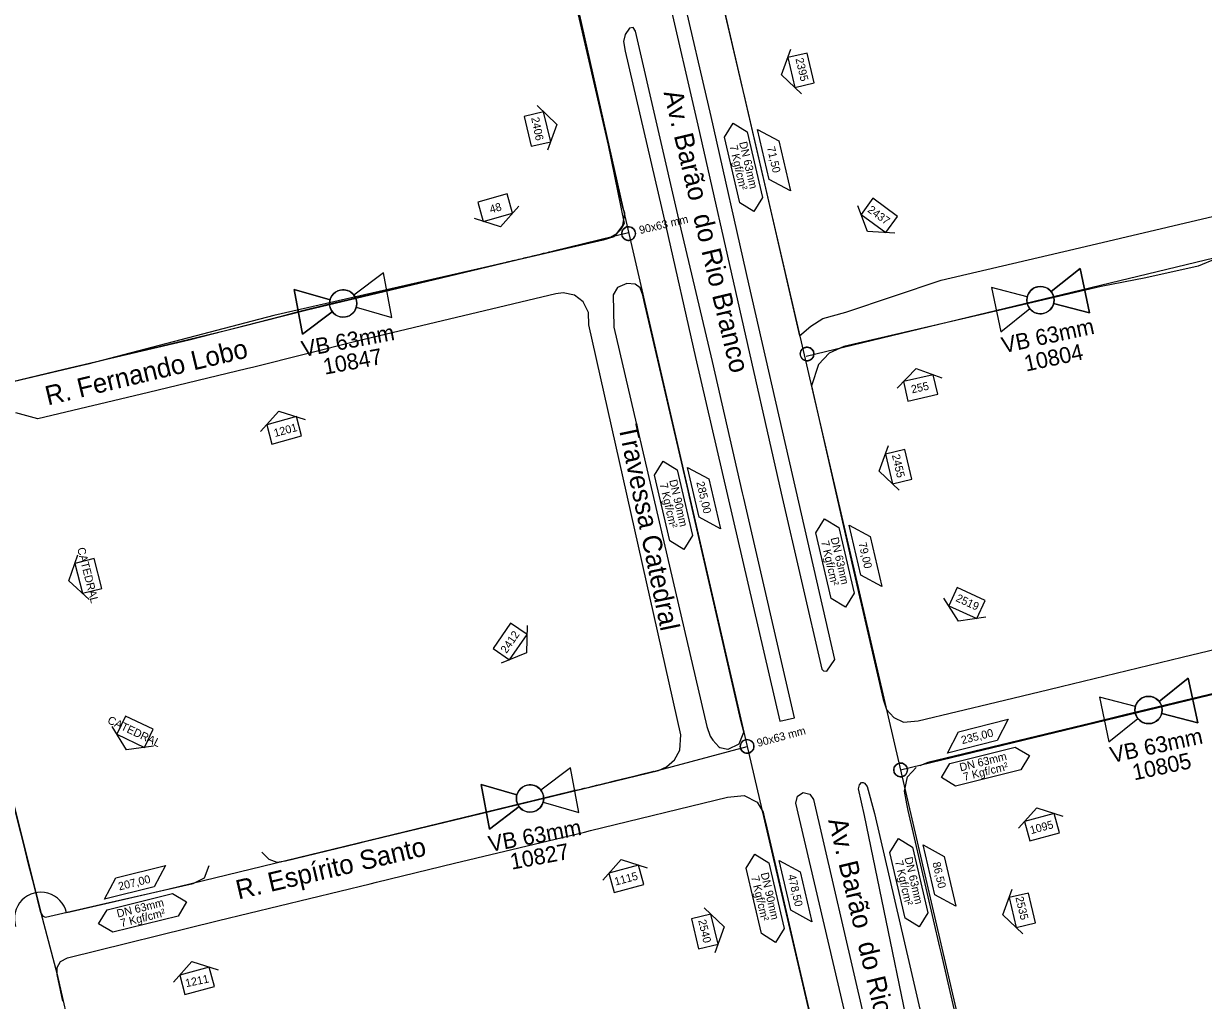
# Model space of a CAD drawing. Extents: x 656692 to 673945, y 7585994 to 7599066.
# Drawn here: x 670030 to 670472.2, y 7593362 to 7593728.2 of the extents above; entities that cross this region are included whole.
import ezdxf

# ---------------------------------------------------------------- set-up
doc = ezdxf.new("R2010")
doc.units = 0
for name, color, linetype in [('FORMATO', 7, 'Continuous'), ('LOGRADOURO', 7, 'Continuous'), ('LOGRADOURO_TEXTO', 7, 'Continuous'), ('NUM_REF', 7, 'Continuous'), ('SIMBOLO', 7, 'Continuous'), ('TEXTO', 7, 'Continuous'), ('TUBO_PEAD_GN_63', 7, 'Continuous'), ('TUBO_PEAD_GN_90', 7, 'Continuous'), ('VALVULA_PEAD_63', 7, 'Continuous')]:
    doc.layers.add(name, color=color, linetype=linetype)

# ---------------------------------------------------------------- blocks, each defined once
blk = doc.blocks.new('INTERLIGACAO_5')
at = {"layer": 'SIMBOLO'}
blk.add_circle((0, 0), 1.28, dxfattribs=at)
for start, end in [(0, 180), (180, 0)]:
    blk.add_arc((0, 0), 1.28, start, end, dxfattribs=at)
blk = doc.blocks.new('VALVULA_PEAD_DN_9')
at = {"layer": 'VALVULA_PEAD_63'}
for points in [[(-1.14, 0.57), (-4.25, 2.13), (-4.25, -2.13), (-1.14, -0.57)], [(-1.14, -0.57), (-4.25, -2.13), (-4.25, 2.13), (-1.14, 0.57)], [(1.14, -0.57), (4.25, -2.13), (4.25, 2.13), (1.14, 0.57)], [(1.14, -0.57), (4.25, -2.13), (4.25, 2.13), (1.14, 0.57)]]:
    blk.add_lwpolyline(points, dxfattribs=at)
blk.add_circle((0, 0), 1.28, dxfattribs=at)
for start, end in [(90, 270), (270, 90), (153.4349, 206.5651), (0, 26.5651), (333.4349, 0)]:
    blk.add_arc((0, 0), 1.28, start, end, dxfattribs=at)
blk = doc.blocks.new('NUM_REF_1')
at = {"layer": 'NUM_REF'}
blk.add_lwpolyline([(-4.3125, 0.9375), (0, 3.75), (4.3125, 0.9375)], dxfattribs=at)
blk.add_lwpolyline([(2.875, -1.875), (2.875, 1.875), (-2.875, 1.875), (-2.875, -1.875)], close=True, dxfattribs=at)

msp = doc.modelspace()

# ---------------------------------------------------------------- linework, layer by layer
at = {"layer": 'LOGRADOURO'}
for p, q in [((670024.02, 7593444.94), (670031.73, 7593414.01)), ((670031.73, 7593414.01), (670032.49, 7593410.8)), ((670032.49, 7593410.8), (670036.58, 7593394.65)), ((670097.78, 7593407.98), (670099.58, 7593412.58)), ((670060.51, 7593398.35), (670093.53, 7593405.81)), ((670093.53, 7593405.81), (670097.78, 7593407.98)), ((670038.28, 7593393.24), (670060.51, 7593398.35)), ((670036.58, 7593394.65), (670037.26, 7593393.55)), ((670037.26, 7593393.55), (670038.28, 7593393.24))]:
    msp.add_line(p, q, dxfattribs=at)
for points in [[(670136.66, 7594169.86), (670162.19, 7594059.36), (670168.87, 7594029.73), (670175.31, 7594002.75), (670179.99, 7593982.77), (670184.4, 7593962.89), (670195.03, 7593917.13), (670204.21, 7593877.89), (670211.92, 7593844.99), (670217.01, 7593822.85), (670221.54, 7593803.12), (670225.32, 7593786.75), (670233.29, 7593752.31), (670242.08, 7593714.06), (670247.91, 7593688.8), (670255.04, 7593653.23), (670253.88, 7593651.05), (670251.21, 7593648.31), (670247.27, 7593647.06), (670216.98, 7593640), (670123.81, 7593618.77), (670054.05, 7593600.53), (670014.86, 7593591.25)], [(670236.15, 7593644.74), (670238.98, 7593645.42), (670241.53, 7593645.89), (670250.03, 7593648.17), (670252.4, 7593649.57), (670254.58, 7593652.54), (670255.31, 7593657.11), (670254.61, 7593659.28), (670234.33, 7593747.36), (670233.58, 7593750.06), (670216.99, 7593822.33), (670208.09, 7593860.47), (670207.48, 7593863.14), (670194.62, 7593918.2)], [(670290.86, 7593740.61), (670299.36, 7593704.14), (670299.9, 7593701.63), (670307.04, 7593670.92), (670320.78, 7593611.18), (670325.01, 7593614.78), (670329.56, 7593617.6), (670338.18, 7593620.03), (670373.95, 7593632), (670423.55, 7593643.65), (670476.13, 7593656.05), (670516.11, 7593665.38), (670567.2, 7593677.24), (670616.08, 7593688.7), (670660.58, 7593699.2), (670708.06, 7593710.35), (670743.57, 7593718.73)], [(670052.85, 7593600.41), (670106.22, 7593613.27), (670111.71, 7593614.61), (670136.24, 7593620.95), (670175.63, 7593630.32), (670218.05, 7593640.34), (670229.18, 7593643.04)], [(670476.87, 7593640), (670470.14, 7593637.23), (670450.59, 7593632.96), (670433.82, 7593629.66), (670388.45, 7593619.06), (670337.43, 7593607.12), (670331.9, 7593604.61), (670327.91, 7593600.47), (670325.25, 7593592.36), (670343.34, 7593513.28), (670343.94, 7593510.7), (670352.1, 7593474.83), (670353.38, 7593471.02), (670356.19, 7593468.05), (670359.76, 7593466.37), (670365.33, 7593466.79), (670394.54, 7593473.78)], [(670119.3, 7593417.6), (670121.96, 7593414.92), (670124.99, 7593413.82), (670128.24, 7593414.3), (670155.54, 7593421), (670157.91, 7593421.59), (670201.54, 7593432.13), (670237.04, 7593440.77), (670239.57, 7593441.3), (670268.02, 7593448.27), (670271.01, 7593449.56), (670274, 7593452.26), (670275.9, 7593455.83), (670276.3, 7593461.63), (670241.81, 7593615.3), (670241.68, 7593619.9), (670239.77, 7593623.87), (670236.44, 7593626.41), (670232.26, 7593627.27), (670229.49, 7593626.87), (670197.55, 7593619.24), (670155, 7593609.11), (670116.28, 7593599.46), (670113.61, 7593598.79), (670076.8, 7593589.97), (670035.32, 7593580.07), (670027.12, 7593582.27)], [(670624.53, 7593346.32), (670665.62, 7593355.7), (670667.59, 7593356.09), (670697.27, 7593362.61), (670702.8, 7593365.37), (670705.69, 7593368.66), (670706.88, 7593370.4), (670708.67, 7593375.24), (670708.85, 7593377.49), (670708.47, 7593380.98), (670699.83, 7593416.77), (670686.44, 7593472.31), (670676.15, 7593514.65), (670664.58, 7593522.51), (670662.69, 7593522.28), (670659.9, 7593521.61), (670621.54, 7593512.36), (670576.82, 7593501.52), (670519.17, 7593487.47), (670442.25, 7593468.96), (670430.14, 7593466), (670368.87, 7593451.23), (670365.85, 7593449.92)], [(670394.54, 7593473.78), (670414.28, 7593478.6), (670418.83, 7593479.69), (670464.25, 7593490.68), (670523.46, 7593504.9), (670525.68, 7593505.41)], [(670624.53, 7593346.32), (670569.73, 7593334.07), (670521.66, 7593323.42), (670475.94, 7593313.21), (670447.99, 7593307.01), (670409.67, 7593298.01), (670407.35, 7593294.02), (670395.17, 7593291.1), (670382.94, 7593340.67), (670382.41, 7593343.17), (670373.98, 7593379.53), (670373.43, 7593381.99), (670361.58, 7593433.22), (670360.99, 7593435.72), (670360.19, 7593440.5), (670361.29, 7593445.84), (670364.54, 7593449.36)], [(670368.76, 7593316.87), (670345.18, 7593431.32), (670342.86, 7593441.38), (670343.24, 7593442.85), (670344.05, 7593443.72), (670344.62, 7593443.73), (670345.2, 7593443.52), (670346.15, 7593442.22), (670348.9, 7593432.15), (670362.09, 7593374.99), (670378.38, 7593304.57)], [(670103.06, 7593391.93), (670159.88, 7593405.67), (670162.27, 7593406.41), (670191.57, 7593413.43), (670240.19, 7593425.15), (670242.51, 7593425.69), (670293.82, 7593438.22), (670300.05, 7593438.85), (670304.88, 7593436.29), (670307.19, 7593432.6), (670307.57, 7593430.88), (670308.2, 7593428.29), (670319.92, 7593377.44), (670330.4, 7593332.55)], [(670370.49, 7593216.23), (670365.31, 7593239.19), (670356.94, 7593275.23), (670346.89, 7593317.85), (670337.18, 7593360.24), (670319.46, 7593435.91), (670320.05, 7593438.64), (670322.19, 7593439.95), (670324.67, 7593439.35), (670325.99, 7593437.38), (670344.66, 7593356.88), (670345.13, 7593355.18), (670357.38, 7593302.46), (670359.16, 7593289.89), (670371.72, 7593216.66), (670383.02, 7593167.92), (670394.57, 7593117.88), (670408.28, 7593058.99), (670415.84, 7593026.27)], [(670044.71, 7593361.7), (670042.62, 7593371.71), (670042.65, 7593374.39), (670043.81, 7593376.6), (670046.45, 7593378.02), (670103.06, 7593391.93)]]:
    msp.add_lwpolyline(points, dxfattribs=at)
for points in [[(670334.05, 7593489.79), (670318.17, 7593559.19), (670301.86, 7593630.62), (670287.68, 7593693.43), (670276.55, 7593741.29), (670275.57, 7593742), (670274.72, 7593741.95), (670272.16, 7593741.39), (670271.35, 7593740.54), (670271.34, 7593739.5), (670282.74, 7593690.13), (670313.95, 7593552.18), (670329.17, 7593486.16), (670329.83, 7593485.58), (670331.04, 7593485.47)], [(670259.33, 7593725.35), (670258.42, 7593726.69), (670257.11, 7593726.44), (670255.52, 7593724.08), (670254.89, 7593721.51), (670255.52, 7593717.82), (670270.76, 7593652.27), (670281.89, 7593603.01), (670313.49, 7593466.65), (670318.89, 7593467.9), (670299.94, 7593550.36), (670299.47, 7593552.3), (670288.25, 7593601.49), (670275.98, 7593653.23)], [(670286.08, 7593464.66), (670287.34, 7593461.1), (670288.34, 7593459.61), (670290.54, 7593457.07), (670290.93, 7593456.85), (670294, 7593456.15), (670294.07, 7593456.2), (670298.16, 7593458.16), (670299.9, 7593462.61), (670299.44, 7593464.52), (670298.78, 7593466.97), (670279.64, 7593550.8), (670279.08, 7593553.13), (670262.6, 7593624.07), (670262.04, 7593626.41), (670261.14, 7593629.11), (670259.17, 7593630.47), (670256.04, 7593630.8), (670252.58, 7593629.3), (670251, 7593626.49), (670251.2, 7593614.44)]]:
    msp.add_lwpolyline(points, close=True, dxfattribs=at)
at = {"layer": 'SIMBOLO'}
for points in [[(670295.93, 7593690.88), (670301.19, 7593687.61), (670306.95, 7593663.03), (670303.69, 7593657.77), (670298.43, 7593661.03), (670292.67, 7593685.62), (670295.93, 7593690.88)], [(670269.74, 7593564.2), (670274.99, 7593560.94), (670280.73, 7593536.35), (670277.47, 7593531.1), (670272.21, 7593534.36), (670266.47, 7593558.95), (670269.74, 7593564.2)], [(670330.22, 7593542.56), (670335.48, 7593539.3), (670341.24, 7593514.71), (670337.98, 7593509.46), (670332.72, 7593512.72), (670326.96, 7593537.3), (670330.22, 7593542.56)], [(670373.97, 7593445.56), (670377.16, 7593450.87), (670401.66, 7593456.97), (670406.96, 7593453.78), (670403.77, 7593448.48), (670379.27, 7593442.38), (670373.97, 7593445.56)], [(670357.93, 7593422.69), (670363.19, 7593419.43), (670368.95, 7593394.84), (670365.69, 7593389.58), (670360.43, 7593392.85), (670354.67, 7593417.43), (670357.93, 7593422.69)], [(670304.02, 7593416.89), (670309.28, 7593413.62), (670315.02, 7593389.03), (670311.75, 7593383.78), (670306.5, 7593387.05), (670300.76, 7593411.63), (670304.02, 7593416.89)], [(670058.12, 7593390.73), (670061.31, 7593396.04), (670085.81, 7593402.14), (670091.11, 7593398.95), (670087.92, 7593393.65), (670063.42, 7593387.55), (670058.12, 7593390.73)]]:
    msp.add_lwpolyline(points, dxfattribs=at)
for points in [[(670309.47, 7593669.8), (670305.09, 7593688.51), (670313.03, 7593684.21), (670317.41, 7593665.5)], [(670283.26, 7593543.12), (670278.89, 7593561.83), (670286.83, 7593557.53), (670291.2, 7593538.81)], [(670343.76, 7593521.48), (670339.38, 7593540.2), (670347.32, 7593535.89), (670351.7, 7593517.18)], [(670394.86, 7593459.4), (670376.21, 7593454.75), (670380.4, 7593462.75), (670399.05, 7593467.4)], [(670371.47, 7593401.61), (670367.09, 7593420.32), (670375.03, 7593416.02), (670379.41, 7593397.31)], [(670317.55, 7593395.8), (670313.18, 7593414.52), (670321.11, 7593410.21), (670325.48, 7593391.49)], [(670079, 7593404.57), (670060.36, 7593399.92), (670064.55, 7593407.92), (670083.2, 7593412.57)]]:
    msp.add_lwpolyline(points, close=True, dxfattribs=at)
at = {"layer": 'TUBO_PEAD_GN_63'}
for p, q in [((670358.69, 7593448.43), (670738.73, 7593540.54)), ((670266.18, 7593447.81), (670301.15, 7593457.23)), ((670084.08, 7593403.63), (670046.23, 7593394.88))]:
    msp.add_line(p, q, dxfattribs=at)
for points in [[(670270.63, 7593828.18), (670395.17, 7593291.1), (670412.62, 7593214.31), (670425.77, 7593159.21), (670458.65, 7593013.14)], [(670036.5, 7593394.83), (670033.94, 7593405.1), (670031.92, 7593413.12), (670030, 7593420.91), (670028.04, 7593428.76), (670026.15, 7593436.44), (670024, 7593445.14), (670021.9, 7593454.01), (670019.78, 7593463.14), (670018.49, 7593468.48), (670017.25, 7593473.7), (670016.34, 7593477.75), (670014.68, 7593485.08), (670012.07, 7593496.69), (670009.27, 7593509.09), (670007.08, 7593519.11), (670004.85, 7593529.26), (670002.82, 7593538.9), (670000.97, 7593547.38), (669998.98, 7593556.44), (669996.99, 7593565.7), (669995.51, 7593572.61), (669992.66, 7593585.75), (669931.57, 7593813.26)], [(670876.88, 7593732.22), (670593.65, 7593668.61), (670323.25, 7593603.37)], [(670256.7, 7593649.76), (670228.59, 7593642.9), (670227.75, 7593642.7), (670226.9, 7593642.49), (670226.21, 7593642.32), (670225.7, 7593642.2), (670224.79, 7593641.98), (670223.95, 7593641.78), (670223.15, 7593641.58), (670222.47, 7593641.42), (670221.96, 7593641.29), (670221.4, 7593641.16), (670220.73, 7593640.99), (670220.05, 7593640.83), (670219.37, 7593640.66), (670218.78, 7593640.52), (670218.13, 7593640.36), (670217.52, 7593640.21), (670216.92, 7593640.08), (670216.21, 7593639.91), (670215.52, 7593639.74), (670214.71, 7593639.55), (670213.98, 7593639.38), (670213.23, 7593639.21), (670212.5, 7593639.03), (670211.8, 7593638.86), (670211.18, 7593638.72), (670210.57, 7593638.57), (670209.75, 7593638.38), (670204.38, 7593637.12), (670199.05, 7593635.86), (670194.77, 7593634.85), (670189.56, 7593633.61), (670184.76, 7593632.49), (670180.86, 7593631.55), (670177.28, 7593630.73), (670171.16, 7593629.26), (670165.44, 7593627.89), (670160.6, 7593626.75), (670155.75, 7593625.61), (670151.81, 7593624.66), (670147.27, 7593623.59), (670143.16, 7593622.61), (670140.15, 7593621.88), (670137.49, 7593621.24), (670134.61, 7593620.54), (670132.06, 7593619.87), (670129.31, 7593619.17), (670126.53, 7593618.45), (670092.03, 7593609.58), (670045.08, 7593598.51), (670002.33, 7593588.33)], [(670266.18, 7593447.81), (670266.14, 7593447.81), (670265.16, 7593447.56), (670262.14, 7593446.82), (670258.19, 7593445.87), (670254.45, 7593444.94), (670251.3, 7593444.17), (670250.36, 7593443.94), (670249.06, 7593443.63), (670247.83, 7593443.32), (670246.93, 7593443.1), (670245.95, 7593442.87), (670245.37, 7593442.72), (670244.63, 7593442.54), (670243.84, 7593442.34), (670243.26, 7593442.2), (670242.4, 7593441.99), (670241.92, 7593441.87), (670241.42, 7593441.75), (670241.02, 7593441.65), (670240.04, 7593441.41), (670239.49, 7593441.28), (670239.1, 7593441.2), (670238.8, 7593441.13), (670237.61, 7593440.89), (670237.08, 7593440.77), (670236.62, 7593440.66), (670236.11, 7593440.54), (670235.76, 7593440.45), (670235.28, 7593440.34), (670235.21, 7593440.32), (670235.16, 7593440.31), (670235.08, 7593440.29), (670235.02, 7593440.27), (670234.92, 7593440.25), (670234.86, 7593440.23), (670234.79, 7593440.22), (670234.69, 7593440.19), (670084.1, 7593403.63)], [(670036.49, 7593394.84), (670042.62, 7593371.71), (670056.94, 7593308.46), (670060.28, 7593293.62), (670061.17, 7593289.64), (670063.93, 7593277.91), (670115.31, 7593058.49), (670129.76, 7592973.31), (670135.69, 7592949.71), (670140.2, 7592938.17), (670145.14, 7592928.13), (670154.31, 7592914.73), (670168.41, 7592898.93), (670188.86, 7592877.64), (670202.82, 7592863.12)]]:
    msp.add_lwpolyline(points, dxfattribs=at)
msp.add_arc((670036.5, 7593392.62), 9.93, 13.2191, 196.6626, dxfattribs=at)
at = {"layer": 'TUBO_PEAD_GN_90'}
msp.add_lwpolyline([(670197.11, 7593914.53), (670254.61, 7593659.28), (670299.9, 7593462.61), (670366.09, 7593178.46), (670413.3, 7592972.1)], dxfattribs=at)

# ---------------------------------------------------------------- block references
at = {"layer": 'FORMATO'}
for p, xscale, yscale, rotation in [((670321.38, 7593710.7), 2, 2, 103.25233689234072), ((670222.6, 7593688.67), 2, 2, -76.67539240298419), ((670206.76, 7593659.2), 1.9999999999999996, 1.9999999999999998, -164.43974362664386), ((670350.73, 7593656.29), 2, 2, 143.8193996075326), ((670366.17, 7593591.63), 2, 2, 12.737713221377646), ((670127.69, 7593575.73), 2, 2, 15.171414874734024), ((670357.97, 7593562.12), 2, 2, 103.25233689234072), ((670054.28, 7593521.15), 1.9999999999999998, 1.9999999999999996, 104.2104213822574), ((670383.56, 7593510.97), 1.9999999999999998, 2.0000000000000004, 155.3437654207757), ((670212.35, 7593496.58), 1.9999999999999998, 1.9999999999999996, -124.58320234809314), ((670071.79, 7593462.75), 2, 2, 154.51740502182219), ((670411.7, 7593426.99), 2, 2, 15.171414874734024), ((670255.94, 7593407.6), 2, 2, 15.171414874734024), ((670404.29, 7593395.82), 2, 2, 103.25233689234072), ((670285.29, 7593387.88), 2, 2, -76.67539240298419), ((670095.06, 7593369.36), 2, 2, 15.171414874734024)]:
    msp.add_blockref('NUM_REF_1', p, dxfattribs=dict(at, xscale=xscale, yscale=yscale, rotation=rotation))
at = {"layer": 'SIMBOLO'}
for p, xscale, yscale, rotation in [((670256.74, 7593649.5), 1.9999999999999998, 2.0000000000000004, -152.2575551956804), ((670323.63, 7593604.35), 2, 2, -14.764722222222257), ((670301.15, 7593457.23), 2, 2, 67.86674283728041), ((670358.69, 7593448.43), 2, 2, -14.764722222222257)]:
    msp.add_blockref('INTERLIGACAO_5', p, dxfattribs=dict(at, xscale=xscale, yscale=yscale, rotation=rotation))
at = {"layer": 'VALVULA_PEAD_63', "yscale": 4.000000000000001}
for p, xscale, rotation in [((670411.1, 7593624.54), 4.000000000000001, -167.8897304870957), ((670149.76, 7593623.29), 3.9999999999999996, 10.574770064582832), ((670451.61, 7593470.89), 4.000000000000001, -167.8897304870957), ((670219.81, 7593437.74), 3.9999999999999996, 10.574770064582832)]:
    msp.add_blockref('VALVULA_PEAD_DN_9', p, dxfattribs=dict(at, xscale=xscale, rotation=rotation))

# ---------------------------------------------------------------- texts
for s, height, rotation, p in [('2395', 3, 283.2523, (670319.26, 7593715.01)), ('2406', 3, 281.8203, (670220.23, 7593692.85)), ('48', 3, 15.5603, (670205.12, 7593657.05)), ('2437', 3, 323.8194, (670346.08, 7593657.83)), ('90x63 mm', 3, 13.3094, (670261.1, 7593649.29)), ('VB 63mm', 6, 10.5748, (670134.79, 7593603.2)), ('VB 63mm', 6, 12.1103, (670397.25, 7593604.62)), ('10847', 6, 10.5748, (670142.89, 7593596.57)), ('10804', 6, 12.1103, (670405.71, 7593597.74)), ('255', 3, 12.7377, (670363, 7593589.57)), ('1201', 3, 15.1714, (670124.24, 7593573.2)), ('2455', 3, 283.2523, (670355.41, 7593566.4)), ('CATEDRAL', 3, 284.2104, (670050.08, 7593531.44)), ('2519', 3, 335.3438, (670379.11, 7593511.81)), ('2412', 3, 55.4168, (670210.99, 7593491.88)), ('CATEDRAL', 3, 334.5174, (670061.19, 7593466.09)), ('90x63 mm', 3, 15.0665, (670305.28, 7593457.02)), ('VB 63mm', 6, 12.1103, (670437.91, 7593451.01)), ('10805', 6, 12.1103, (670446.24, 7593444.48)), ('VB 63mm', 6, 10.5748, (670204.84, 7593417.65)), ('1095', 3, 15.1714, (670407.6, 7593424.33)), ('10827', 6, 10.5748, (670212.94, 7593411.02)), ('1115', 3, 15.1714, (670251.88, 7593405.05)), ('2535', 3, 283.2523, (670401.7, 7593400.63)), ('2540', 3, 283.3246, (670282.81, 7593392)), ('1211', 3, 11.7952, (670090.96, 7593366.97))]:
    msp.add_text(s, height=height, rotation=rotation).set_placement(p)
at = {"layer": 'LOGRADOURO_TEXTO'}
for s, rotation, p in [('Av. Barão  do Rio Branco', 283.441, (670269.83, 7593702.4)), ('R. Fernando Lobo', 13.4908, (670039.11, 7593585.05)), ('Travessa Catedral', 281.7075, (670252.91, 7593577.15)), ('Av. Barão  do Rio Branco', 283.441, (670331.52, 7593429.56)), ('R. Espírito Santo', 13.1895, (670110.53, 7593399.86))]:
    msp.add_text(s, height=7.2, rotation=rotation, dxfattribs=at).set_placement(p)
at = {"layer": 'TEXTO'}
for s, rotation, p in [('DN 63mm', 283.1838, (670298.15, 7593683.62)), ('7 Kgf/cm²', 283.1838, (670294.55, 7593682.3)), ('71,50', 283.1838, (670308.59, 7593681.77)), ('7 Kgf/cm²', 283.1431, (670268.35, 7593555.63)), ('DN 90mm', 283.1431, (670271.95, 7593556.95)), ('285,00', 283.1431, (670282.13, 7593556.22)), ('7 Kgf/cm²', 283.1838, (670328.84, 7593533.98)), ('DN 63mm', 283.1838, (670332.44, 7593535.3)), ('79,00', 283.1838, (670342.88, 7593533.45)), ('235,00', 13.9888, (670381.77, 7593458.07)), ('DN 63mm', 13.9888, (670381.19, 7593447.88)), ('7 Kgf/cm²', 13.9888, (670382.56, 7593444.3)), ('7 Kgf/cm²', 283.1838, (670356.55, 7593414.11)), ('DN 63mm', 283.1838, (670360.14, 7593415.43)), ('DN 90mm', 283.1431, (670306.23, 7593409.63)), ('86,50', 283.1838, (670370.59, 7593413.58)), ('207,00', 13.9888, (670065.92, 7593403.24)), ('7 Kgf/cm²', 283.1431, (670302.64, 7593408.32)), ('478,50', 283.1431, (670316.41, 7593408.9)), ('DN 63mm', 13.9888, (670065.34, 7593393.05)), ('7 Kgf/cm²', 13.9888, (670066.71, 7593389.47))]:
    msp.add_text(s, height=3, rotation=rotation, dxfattribs=at).set_placement(p)

doc.saveas('drawing.dxf')
